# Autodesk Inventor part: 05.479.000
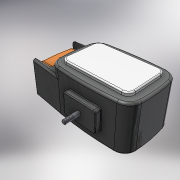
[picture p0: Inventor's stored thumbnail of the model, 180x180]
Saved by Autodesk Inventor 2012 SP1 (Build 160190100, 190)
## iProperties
Created: 2005-07
Part Number: 05.479.000
Material: ABS Plastic
Document SubType Name: Modeling
Designer: PVitaliy
Manufacturer: Standard
Standards Organization: Custom
Density: 1 g/cm^3
Author: PVitaliy
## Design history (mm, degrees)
sketch "Эскиз2"
  geometry: L1 (0, 0)-(200, 0); L2 (200, 0)-(200, 140); L3 (200, 140)-(0, 140); L4 (0, 140)-(0, 0); L5 (-150, 70)-(350, 70); L6 (100, 800)-(100, -660); A1 r 800 centre (100, -660) between (200, 133.725) and (0, 133.725); A2 r 800 centre (100, 800) between (0, 6.275) and (200, 6.275); A3 r 350 centre (350, 70) between (5.986, 134.457) and (5.986, 5.543); A4 r 350 centre (-150, 70) between (194.014, 5.543) and (194.014, 134.457); 2 further points
  constraints: 14 point on circle, 12 end point, 6 point on line, 4 centre point, 4 tangent, 2 equal radius, 2 horizontal, 2 parallel, 1 coincident, 1 perpendicular, 1 vertical, 1 other
  dimensions: "d0" = 140 distance of L3.end L1.start; "d1" = 200 distance of L1.start L1.end; "d2" = 800 radius of A1; "d3" = 350 radius of A3
extrude "Выдавливание1" new body sketch "Эскиз2" distance "d4" = 120; taper "d5" = 0 deg
fillet "Сопряжение1" dims "d6" = 30
sketch "Эскиз3"
  geometry: L1 (-29.503, 136.888)-(62, 128.793); L2 (62, 128.793)-(62, 11.207); L3 (-29.503, 3.112)-(62, 11.207); L4 (62, 122.793)-(12, 122.793); L5 (12, 122.793)-(12, 17.207); L6 (12, 17.207)-(62, 17.207); A1 r 30 centre (-32.147, 32.995) between (-29.503, 3.112) and (-2.348, 29.526) reference; A2 r 350 centre (-350, 70) between (-2.348, 29.526) and (-2.348, 110.474) reference; A3 r 30 centre (-32.147, 107.005) between (-2.348, 110.474) and (-29.503, 136.888) reference; A4 r 800 centre (-100, -660) between (-29.503, 136.888) and (-170.497, 136.888) reference; A5 r 350 centre (150, 70) between (-197.652, 110.474) and (-197.652, 29.526) reference; A6 r 800 centre (-100, 800) between (-170.497, 3.112) and (-29.503, 3.112) reference
  constraints: 12 end point, 4 tangent, 2 horizontal, 2 point on line, 2 vertical, 1 point on circle
  dimensions: "d7" = 262 distance edge to line of A5 L2; "d8" = 6 distance from line of L4 L1.end; "d9" = 6 distance from line of L6 L2.end; "d10" = 50 distance between parallel lines of L5 L2
extrude "Выдавливание2" join sketch "Эскиз3" distance "d11" = 90; taper "d12" = 0 deg
sketch "Эскиз4"
  geometry: L1 (90, 0)-(90, 105.586) reference; L2 (0, 105.586)-(90, 105.586) reference; L3 (0, 0)-(0, 105.586) reference; L4 (0, 0)-(90, 0) reference; L5 (8, 101.586)-(82, 101.586); L6 (82, 101.586)-(82, 4); L7 (82, 4)-(8, 4); L8 (8, 4)-(8, 101.586)
  constraints: 8 end point, 2 horizontal, 1 parallel, 1 vertical
  dimensions: "d14" = 4 distance between parallel lines of L5 L2; "d15" = 4 distance between parallel lines of L7 L4; "d16" = 8 distance between parallel lines of L8 L3; "d17" = 8 distance between parallel lines of L1 L6
extrude "Выдавливание3" join sketch "Эскиз4" distance "d18" = 50; taper "d19" = -3 deg
sketch "Эскиз5"
  geometry: L1 (-62, 23.827)-(-62, 116.173) reference; L2 (-12, 118.793)-(-62, 116.173) reference; L3 (-12, 21.207)-(-62, 23.827) reference; L4 (-59, 116.33)-(-59, 23.67); A1 r 359.242 centre (297.242, 70) between (-59, 116.33) and (-59, 23.67); 1 further point
  constraints: 3 point on circle, 2 end point, 2 point on line, 1 centre point, 1 midpoint, 1 tangent, 1 vertical
  dimensions: "d21" = 3 distance between parallel lines of L1 L4
extrude "Выдавливание4" cut sketch "Эскиз5" stored distance "d22" = 50; taper "d23" = 0 deg
sketch "Эскиз6"
  geometry: L1 (20, 120)-(180, 120); L2 (180, 120)-(180, 20); L3 (180, 20)-(20, 20); L4 (20, 20)-(20, 120); A1 r 30 centre (32.147, 32.995) between (2.348, 29.526) and (29.503, 3.112) reference; A2 r 800 centre (100, 800) between (29.503, 3.112) and (170.497, 3.112) reference; A3 r 30 centre (167.853, 32.995) between (170.497, 3.112) and (197.652, 29.526) reference; A4 r 350 centre (-150, 70) between (197.652, 29.526) and (197.652, 110.474) reference; A5 r 30 centre (167.853, 107.005) between (197.652, 110.474) and (170.497, 136.888) reference; A6 r 800 centre (100, -660) between (170.497, 136.888) and (29.503, 136.888) reference; A7 r 30 centre (32.147, 107.005) between (29.503, 136.888) and (2.348, 110.474) reference; A8 r 350 centre (350, 70) between (2.348, 110.474) and (2.348, 29.526) reference
  constraints: 8 end point, 2 parallel, 1 horizontal, 1 perpendicular
  dimensions: "d24" = 20 distance edge to line of A6 L1; "d25" = 20 distance edge to line of A2 L3 (= d24); "d26" = 20 distance edge to line of A4 L2 (= d24); "d27" = 20 distance edge to line of A8 L4 (= d24)
extrude "Выдавливание5" cut sketch "Эскиз6" distance "d28" = 8; taper "d29" = 0 deg
node "РабПлоскость1"
sketch "Эскиз8"
  geometry: L1 (0, 90)-(0, 112) reference; L2 (-200, 0)-(-200, 112) reference; L3 (0, 112)-(-200, 112); L4 (-100, 112)-(-100, 0); L5 (-170.497, 0)-(-29.503, 0) reference; L6 (-60, 82)-(-140, 82); L7 (-140, 82)-(-140, 30); L8 (-140, 30)-(-60, 30); L9 (-60, 30)-(-60, 82); 1 further point
  constraints: 12 end point, 3 midpoint, 2 horizontal, 2 parallel, 1 perpendicular, 1 point on line, 1 vertical
  dimensions: "d31" = 30 distance between parallel lines of L6 L3; "d32" = 30 distance between parallel lines of L8 L5; "d33" = 80 distance of L6.start L6.end
extrude "Выдавливание6" join sketch "Эскиз8" stored distance "d34" = 8; taper "d35" = 0 deg
sketch "Эскиз9"
  geometry: L1 (60, 82)-(140, 82) reference; L2 (60, 30)-(60, 82) reference; L3 (140, 30)-(60, 30) reference; L4 (140, 82)-(140, 30) reference; L5 (100, 82)-(100, 30); L6 (60, 56)-(140, 56); C1 r 5 at (100, 56)
  constraints: 5 midpoint, 4 end point, 1 centre point
  dimensions: "d36" = 10 diameter of C1
extrude "Выдавливание7" join sketch "Эскиз9" distance "d37" = 35; taper "d38" = 0 deg
fillet "Сопряжение2" dims "d39" = 15, "d40" = 5, "d41" = 3
fillet "Сопряжение3" dims "d42" = 8
fillet "Сопряжение4" dims "d43" = 5
fillet "Сопряжение5" dims "d44" = 2
chamfer "Фаска1" distance "d45" = 1; stored, may be unused: second distance "d46" = 2, angle "d47" = 45 deg
feature "Резьба1" dims "d48" = 20, "d49" = 0
body "Solid1"
other parameters: "d30" = -12.5
